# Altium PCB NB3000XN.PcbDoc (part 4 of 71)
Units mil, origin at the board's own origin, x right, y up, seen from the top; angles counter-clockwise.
Board outline 9527.56 x 6929.77 mil, 6 copper layers (Top Layer, GND+SHIELD, MidLayer1, MidLayer2, P2 - 3V3+5V0, Bottom Layer), stack 62.375 mil thick; 832 components, 1027 nets, 4655 pads, 4981 vias.
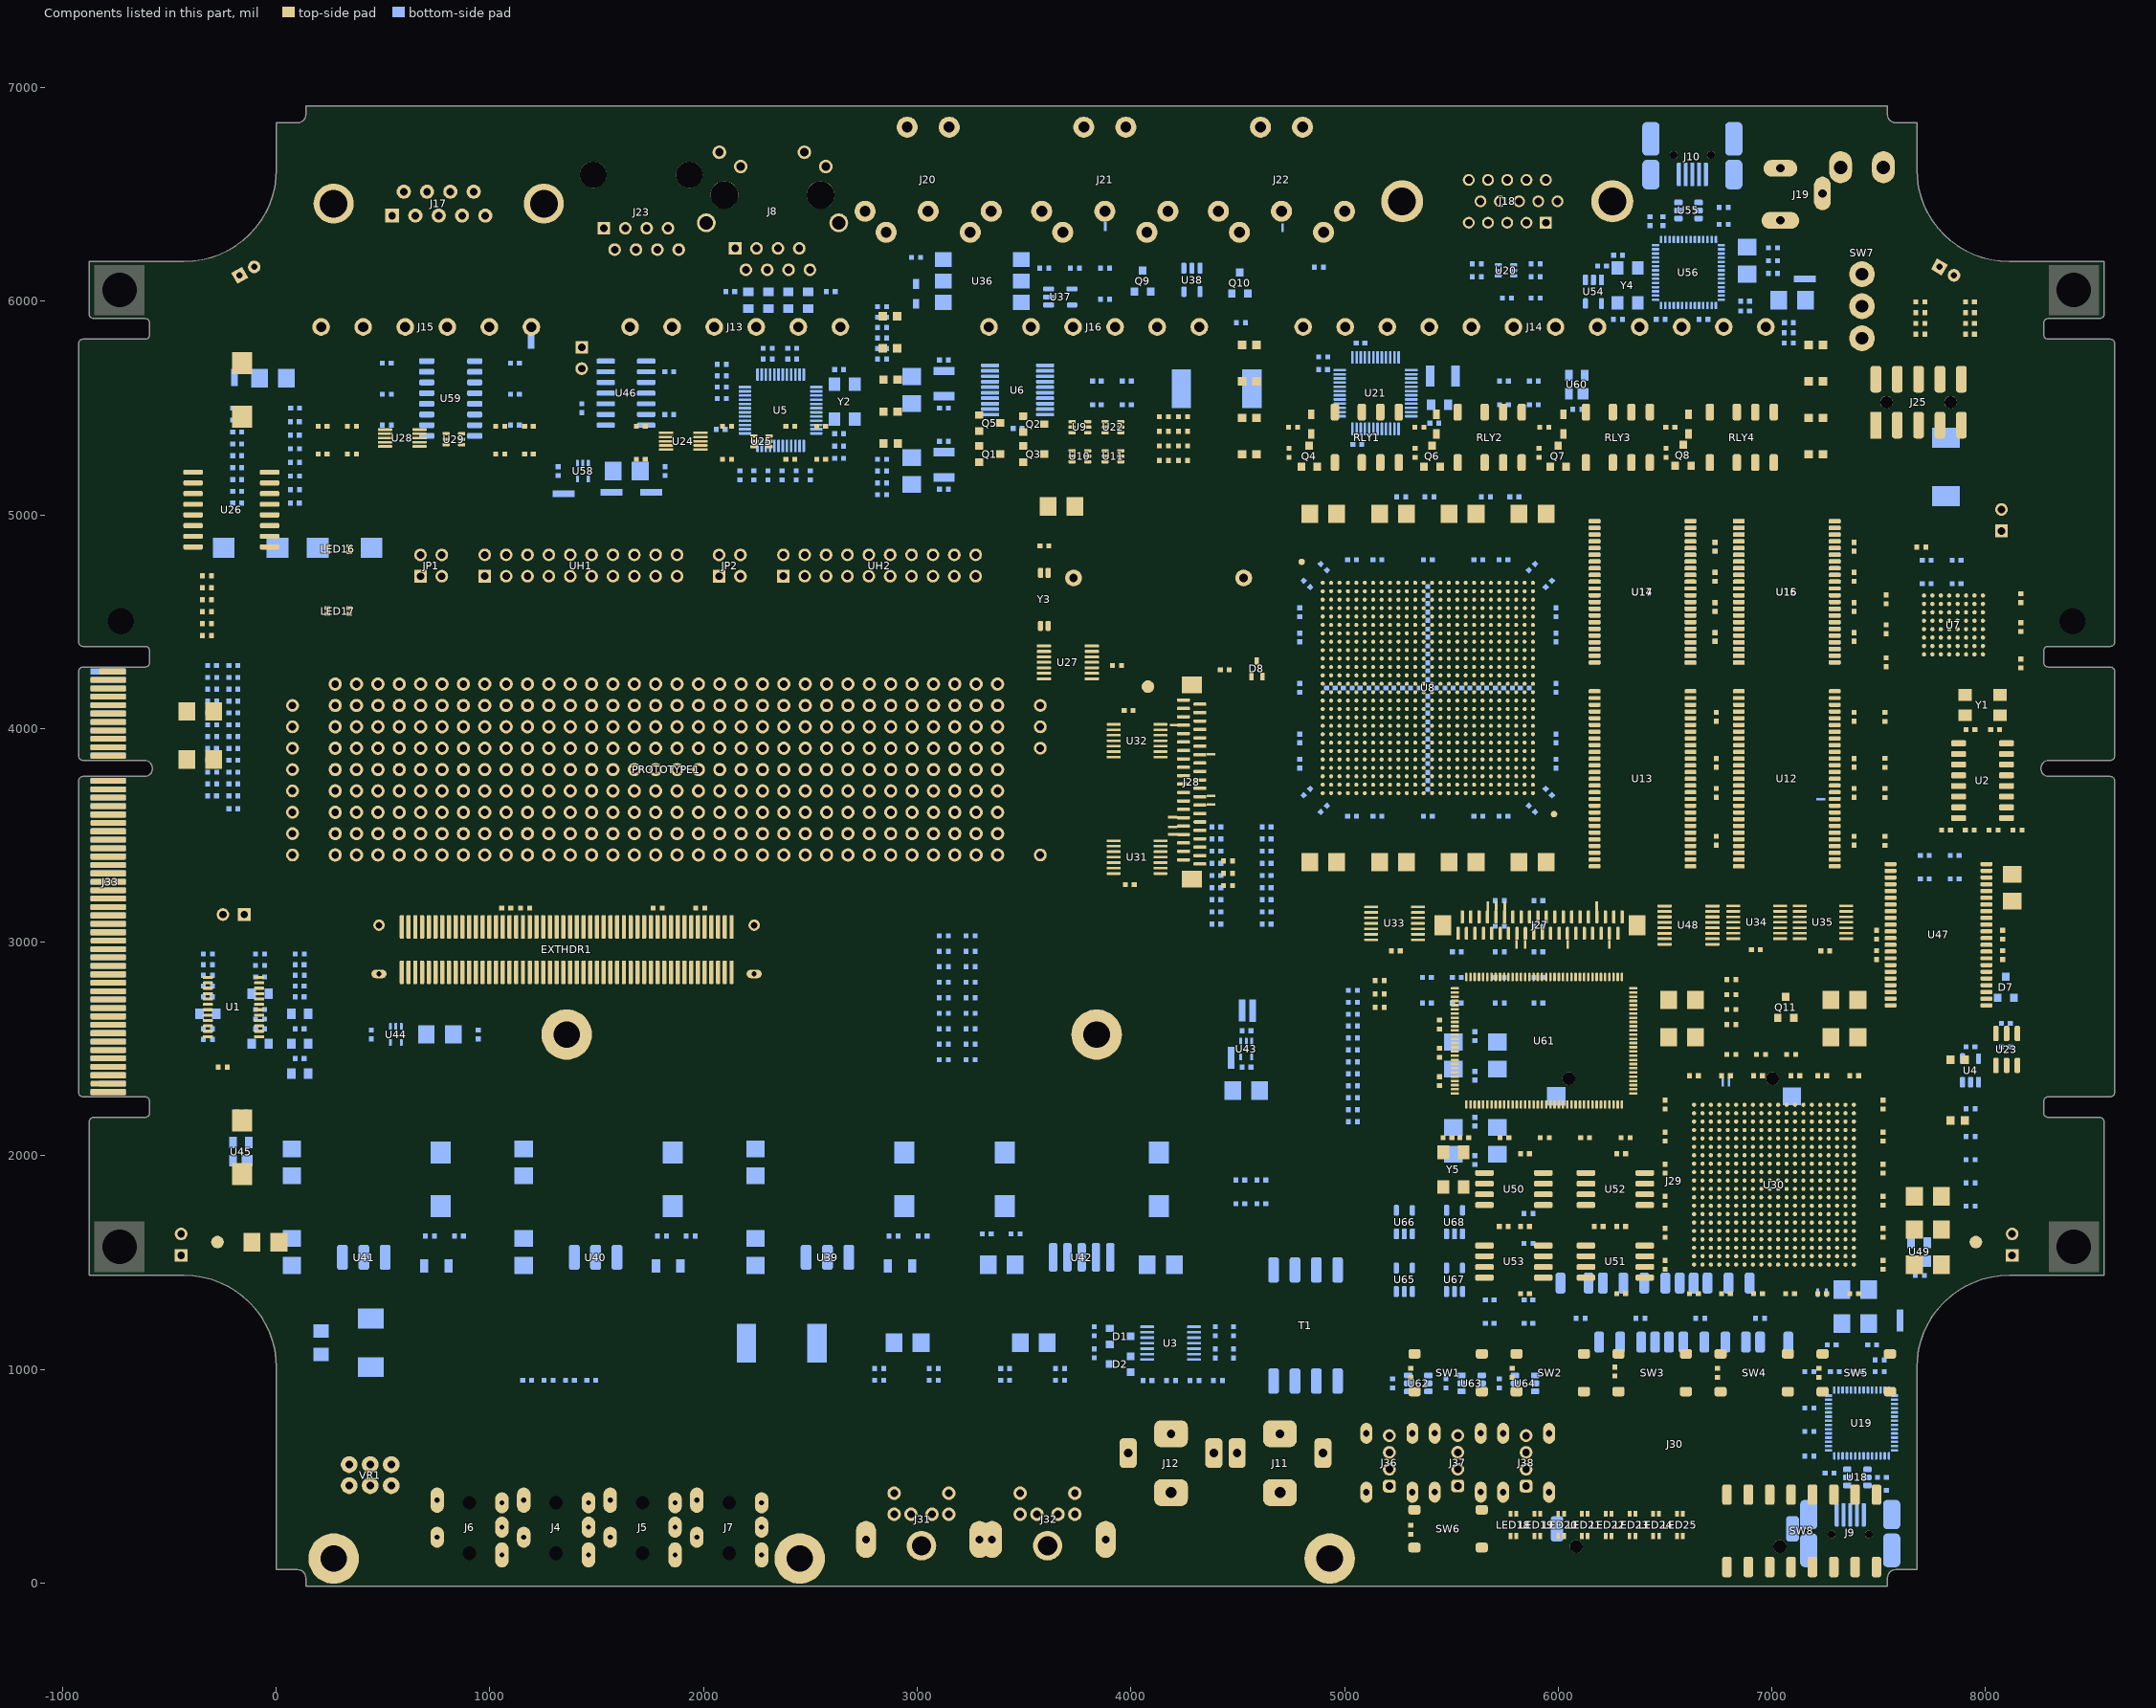
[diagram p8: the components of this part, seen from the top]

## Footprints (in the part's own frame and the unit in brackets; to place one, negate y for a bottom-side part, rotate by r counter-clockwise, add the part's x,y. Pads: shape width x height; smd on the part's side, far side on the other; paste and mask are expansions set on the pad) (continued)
S1204RGBSDJC [mm]
  rect 0.7x0.45 smd paste-1 mask+0: 1(1.313,-0.345)
  rect 0.7x0.45 smd paste-1 mask+0.102: 2(-1.313,-0.353) 3(-1.313,0.345)
  rect 0.7x0.45 smd paste-1: 4(1.313,0.343)
  silkscreen extent -2.19,-0.05 -2.09,0.05, body extent -1.49,-0.46 1.47,0.47, height 1.8
SC70_6L [mm]
  rrect50% 0.4x0.85 smd: 1(0,0) 2(0.65,0) 3(1.3,0) 4(1.3,1.85) 5(0.65,1.85) 6(0,1.85)
  silkscreen extent -0.8,-0.55 1.8,1.85, body extent -0.43,-0.38 1.73,2.22, height 0.64
SOD323 [mil] "SOD-323/SC-76; 2 Leads; Body 1.7 x 1.3 mm, (LxW)"
  rect 45x30 smd: 1(-46.26,0) 2(46.26,0)
  silkscreen extent -37,-30 37,30, body extent -39,-27 38,28, height 20
SOIC8-200-BODY [mm] "SOIC (JEDEC) 8 PIN, 200 mils body width"
  rrect50% 0.7x2.2 smd: 1(0,0) 2(1.27,0) 3(2.54,0) 4(3.81,0) 5(3.81,7) 6(2.54,7) 7(1.27,7) 8(0,7)
  silkscreen extent -1.34,0.54 4.4,5.4, body extent -0.7,0.12 4.71,6.88, height 1.06
SOIC127P600-14N [mm] "SOIC, 14-Leads, Body 8.7x3.9mm, Pitch 1.27mm, IPC Medium Density"
  rrect50% 2.2x0.6 smd: 1(-2.4,3.81) 2(-2.4,2.54) 3(-2.4,1.27) 4(-2.4,0) 5(-2.4,-1.27) 6(-2.4,-2.54) 7(-2.4,-3.81) 8(2.4,-3.81) 9(2.4,-2.54) 10(2.4,-1.27) 11(2.4,0) 12(2.4,1.27) 13(2.4,2.54) 14(2.4,3.81)
  silkscreen extent -2.53,-4.4 0.9,4.78, body extent -2.88,-4.28 2.92,4.28, height 1.75
SOIC127P600-16 [mm]
  rrect50% 0.7x1.8 smd: 1(-4.445,-2.85) 2(-3.175,-2.85) 3(-1.905,-2.85) 4(-0.635,-2.85) 5(0.635,-2.85) 6(1.905,-2.85) 7(3.175,-2.85) 8(4.445,-2.85) 9(4.445,2.85) 10(3.175,2.85) 11(1.905,2.85) 12(0.635,2.85) 13(-0.635,2.85) 14(-1.905,2.85) 15(-3.175,2.85) 16(-4.445,2.85)
  silkscreen extent -5.42,-2.72 5,1.1, body extent -4.9,-2.87 4.9,2.93, height 1.75
SOIC127P1030-16N [mm] "SOIC, 16-Leads, Body 10.3x7.5mm, Pitch 1.27mm, IPC Medium Density"
  rrect50% 2.3x0.6 smd: 1(-4.55,4.445) 2(-4.55,3.175) 3(-4.55,1.905) 4(-4.55,0.635) 5(-4.55,-0.635) 6(-4.55,-1.905) 7(-4.55,-3.175) 8(-4.55,-4.445) 9(4.55,-4.445) 10(4.55,-3.175) 11(4.55,-1.905) 12(4.55,-0.635) 13(4.55,0.635) 14(4.55,1.905) 15(4.55,3.175) 16(4.55,4.445)
  silkscreen extent -4.67,-5.25 3,5.42, body extent -4.9,-5.25 4.89,5.25, height 2.65
SOP65P780-20 [mm]
  rrect50% 0.45x2.15 smd: 1(-2.925,-3.275) 2(-2.275,-3.275) 3(-1.625,-3.275) 4(-0.975,-3.275) 5(-0.325,-3.275) 6(0.325,-3.275) 7(0.975,-3.275) 8(1.625,-3.275) 9(2.275,-3.275) 10(2.925,-3.275) 11(2.925,3.275) 12(2.275,3.275) 13(1.625,3.275) 14(0.975,3.275) 15(0.325,3.275) 16(-0.325,3.275) 17(-0.975,3.275) 18(-1.625,3.275) 19(-2.275,3.275) 20(-2.925,3.275)
  silkscreen extent -3.8,-3.4 3.75,1.8, body extent -3.33,-3.33 3.43,3.28, height 1
SOT65P210X80-5N [mm] "SOT23, 5-Leads, Body 2.0x2.1mm (max), Pitch 0.65mm, IPC Medium Density"
  rrect50% 0.8x0.35 smd: 1(-0.95,0.65) 2(-0.95,0) 3(-0.95,-0.65) 4(0.95,-0.65) 5(0.95,0.65)
  silkscreen extent -1.07,-1 0.15,1.5, body extent -1.02,-0.99 0.9,0.99, height 0.57
SOT95P230-3C [mm] "SOT23, 1=bottom-left, 2=bottom-right, 3=top"
  rect 0.9x0.95 smd: 1(-0.95,-1.25) 2(0.95,-1.25) 3(0,1.25)
  silkscreen extent -1.3,-0.38 1.3,1.25, body extent -1.14,-1.18 1.17,1.44, height 0.38
SOT95P230-3D [mm] "SOT23, 1=bottom-left, 2=top, 3=bottom-right"
  rect 0.9x0.95 smd: 1(-0.95,-1.25) 2(0,1.25) 3(0.95,-1.25)
  silkscreen extent -1.3,-0.38 1.3,1.25, body extent -1.14,-1.25 1.17,1.36, height 0.38
SOT95P280-5 [mm] "SOT-23/SC-74A; 5 Leads; Body 3.1 x 3 mm, inc. leads (LxW max)33"
  rrect50% 0.6x1.3 smd: 1(-0.95,-1.4) 2(0,-1.4) 3(0.95,-1.4) 4(0.95,1.4)
  rrect50% 0.6x1.25 smd: 5(-0.95,1.4)
  silkscreen extent -1.55,-0.9 1.55,0.9, body extent -1.45,-1.45 1.45,1.35, height 0.77
SOT143 [mm] "SOT-143; 4 Leads; Body 3 x 2.6 mm, inc. leads (LxW max)"
  rect 1.35x1.35 smd: 1(-0.75,-1.1)
  rect 0.9x1.35 smd: 2(0.95,-1.1) 3(0.95,1.1) 4(-0.95,1.1)
  silkscreen extent -1.88,-2.22 1.75,0.7, body extent -1.52,-1.5 1.51,1.46, height 0.8
SOT323-3AL [mm] "SOT323, 3-Leads, Body 2.0x1.3mm, Pitch 0.65mm, Lead Span 2.1mm, IPC High Density"
  rect 0.9x0.508 smd: 1(-0.9,0.65) 2(-0.9,-0.65) 3(0.9,0)
  silkscreen extent -1.02,-1.1 0.7,1.57, body extent -0.7,-1.1 0.7,1.1, height 1
SOT425-1 [mm] "LQFP128: plastic low profile quad flat package; 128 leads; body 14 x 20 x 1.4 mm"
  rrect50% 0.305x0.975 smd mask+0.05: 1(0,0) 2(0.5,0) 3(1,0) 4(1.5,0) 5(2,0) 6(2.5,0) 7(3,0) 8(3.5,0) 9(4,0) 10(4.5,0) 11(5,0) 12(5.5,0) 13(6,0) 14(6.5,0) 15(7,0) 16(7.5,0) 17(8,0) 18(8.5,0) 19(9,0) 20(9.5,0) 21(10,0) 22(10.5,0) 23(11,0) 24(11.5,0) 25(12,0) 26(12.5,0) 27(13,0) 28(13.5,0) 29(14,0) 30(14.5,0) 31(15,0) 32(15.5,0) 33(16,0) 34(16.5,0) 35(17,0) 36(17.5,0) 37(18,0) 38(18.5,0) 65(18.5,15.172) 66(18,15.172) 67(17.5,15.172) 68(17,15.172) 69(16.5,15.172) 70(16,15.172) 71(15.5,15.172) 72(15,15.172) 73(14.5,15.172) 74(14,15.172) 75(13.5,15.172) 76(13,15.172) 77(12.5,15.172) 78(12,15.172) 79(11.5,15.172) 80(11,15.172) 81(10.5,15.172) 82(10,15.172) 83(9.5,15.172) 84(9,15.172) 85(8.5,15.172) 86(8,15.172) 87(7.5,15.172) 88(7,15.172) 89(6.5,15.172) 90(6,15.172) 91(5.5,15.172) 92(5,15.172) 93(4.5,15.172) 94(4,15.172) 95(3.5,15.172) 96(3,15.172) 97(2.5,15.172) 98(2,15.172) 99(1.5,15.172) 100(1,15.172) 101(0.5,15.172) 102(0,15.172)
  rrect50% 0.975x0.305 smd mask+0.05: 39(19.861,1.32) 40(19.861,1.82) 41(19.861,2.32) 42(19.861,2.82) 43(19.861,3.32) 44(19.861,3.82) 45(19.861,4.32) 46(19.861,4.82) 47(19.861,5.32) 48(19.861,5.82) 49(19.861,6.32) 50(19.861,6.82) 51(19.861,7.32) 52(19.861,7.82) 53(19.861,8.32) 54(19.861,8.82) 55(19.861,9.32) 56(19.861,9.82) 57(19.861,10.32) 58(19.861,10.82) 59(19.861,11.32) 60(19.861,11.82) 61(19.861,12.32) 62(19.861,12.82) 63(19.861,13.32) 64(19.861,13.82) 103(-1.35,13.82) 104(-1.35,13.32) 105(-1.35,12.82) 106(-1.35,12.32) 107(-1.35,11.82) 108(-1.35,11.32) 109(-1.35,10.82) 110(-1.35,10.32) 111(-1.35,9.82) 112(-1.35,9.32) 113(-1.35,8.82) 114(-1.35,8.32) 115(-1.35,7.82) 116(-1.35,7.32) 117(-1.35,6.82) 118(-1.35,6.32) 119(-1.35,5.82) 120(-1.35,5.32) 121(-1.35,4.82) 122(-1.35,4.32) 123(-1.35,3.82) 124(-1.35,3.32) 125(-1.35,2.82) 126(-1.35,2.32) 127(-1.35,1.82) 128(-1.35,1.32)
  silkscreen extent -0.66,0.68 19.26,14.49, body extent -1.67,-0.34 20.2,15.54, height 1.61
STANDOFF_SOLDER_3MM#1 [mm] "Non-plated hole for 3mm Soldered Standoff"
  round 6 / inner round 5 / far side round 5 hole 3.15 mask+0.1: STAND(0,0)
  Top Layer circle w0.254: c0,0 r3.3
  Top Layer circle w1: c0,0 r2.2
  Bottom Layer lines w0.4: 3.3,3.3 3.3,-3.3 -3.3,-3.3 -3.3,3.3 3.3,3.3
  body extent -2.76,-2.76 2.74,2.74, height 8.5
STANDOFF_SOLDER_3MM#2 [mm] "Non-plated hole for 3mm Soldered Standoff"
  round 6 / inner round 5 / far side round 5 hole 3.15: STAND(0,0)
  Top Layer circle w0.254: c0,0 r3.3
  Top Layer circle w1: c0,0 r2.2
  Bottom Layer lines w0.635: 3.3,3.3 3.3,-3.3 -3.3,-3.3 -3.3,3.3 3.3,3.3
  body extent -2.76,-2.76 2.74,2.74, height 8.5
SW_DTSM-61NT/R [mil] "Switch, Push Button, Thru-Hole; 4 Leads; Body 8.5 x 8.5 mm (LxW typ); Row Spacing 9.0 mm; Pitch 4.5 mm"
  rrect50% 57x45 smd: 1(157.87,-88.58) 2(-157.48,-88.58) 3(157.87,88.19) 4(-157.48,88.19)
  silkscreen extent -124,-124 124,124, body extent -177,-122 177,122, height 177
T8019L-TNQ [mm]
  round 3.048 hole 1.5: 1(0,20.142) 2(0,23.952) 3(0,27.762)
  oval 2.7x3.81 hole 1.6: S1(2.54,7.442) S2(-2.54,7.442)
  silkscreen extent -3.43,0 3.43,26.11, body extent -3.5,-8.38 3.5,28.01, height 13
TESTPIN [mil]
  round 60 hole 35.43: 1(0,0)
  silkscreen extent -41,-39 156,39
TESTPOINT_ARRAY [mil]
  round 62 hole 35.43: 1(0,0) 2(100,0) 3(200,0) 4(300,0) 5(400,0) 6(500,0) 7(600,0) 8(700,0) 9(800,0) 10(900,0) 11(1000,0) 12(1100,0) 13(1200,0) 14(1300,0) 15(1400,0) 16(1500,0) 17(1600,0) 18(1700,0) 19(1800,0) 20(1900,0) 21(2000,0) 22(2100,0) 23(2200,0) 24(2300,0) 25(2400,0) 26(2500,0) 27(2600,0) 28(2700,0) 29(2800,0) 30(2900,0) 31(3000,0) 32(3100,0) A1(0,700) A2(100,700) A3(200,700) A4(300,700) A5(400,700) A6(500,700) A7(600,700) A8(700,700) A9(800,700) A10(900,700) A11(1000,700) A12(1100,700) A13(1200,700) A14(1300,700) A15(1400,700) A16(1500,700) A17(1600,700) A18(1700,700) A19(1800,700) A20(1900,700) A21(2000,700) A22(2100,700) A23(2200,700) A24(2300,700) A25(2400,700) A26(2500,700) A27(2600,700) A28(2700,700) A29(2800,700) A30(2900,700) A31(3000,700) A32(3100,700) B1(0,600) B2(100,600) B3(200,600) B4(300,600) B5(400,600) B6(500,600) B7(600,600) B8(700,600) B9(800,600) B10(900,600) B11(1000,600) B12(1100,600) B13(1200,600) B14(1300,600) B15(1400,600) B16(1500,600) B17(1600,600) B18(1700,600) B19(1800,600) B20(1900,600) B21(2000,600) B22(2100,600) B23(2200,600) B24(2300,600) B25(2400,600) B26(2500,600) B27(2600,600) B28(2700,600) B29(2800,600) B30(2900,600) B31(3000,600) B32(3100,600) C1(0,500) C2(100,500) C3(200,500) C4(300,500) C5(400,500) C6(500,500) C7(600,500) C8(700,500) C9(800,500) C10(900,500) C11(1000,500) C12(1100,500) C13(1200,500) C14(1300,500) C15(1400,500) C16(1500,500) C17(1600,500) C18(1700,500) C19(1800,500) C20(1900,500) C21(2000,500) C22(2100,500) C23(2200,500) C24(2300,500) C25(2400,500) C26(2500,500) C27(2600,500) C28(2700,500) C29(2800,500) C30(2900,500) C31(3000,500) C32(3100,500) D1(0,400) D2(100,400) D3(200,400) D4(300,400) D5(400,400) D6(500,400) D7(600,400) D8(700,400) D9(800,400) D10(900,400) D11(1000,400) D12(1100,400) D13(1200,400) D14(1300,400) D15(1400,400) D16(1500,400) D17(1600,400) D18(1700,400) D19(1800,400) D20(1900,400) D21(2000,400) D22(2100,400) D23(2200,400) D24(2300,400) D25(2400,400) D26(2500,400) D27(2600,400) D28(2700,400) D29(2800,400) D30(2900,400) D31(3000,400) D32(3100,400) E1(0,300) E2(100,300) E3(200,300) E4(300,300) E5(400,300) E6(500,300) E7(600,300) E8(700,300) E9(800,300) E10(900,300) E11(1000,300) E12(1100,300) E13(1200,300) E14(1300,300) E15(1400,300) E16(1500,300) E17(1600,300) E18(1700,300) E19(1800,300) E20(1900,300) E21(2000,300) E22(2100,300) E23(2200,300) E24(2300,300) E25(2400,300) E26(2500,300) E27(2600,300) E28(2700,300) E29(2800,300) E30(2900,300) E31(3000,300) E32(3100,300) F1(0,200) F2(100,200) F3(200,200) F4(300,200) F5(400,200) F6(500,200) F7(600,200) F8(700,200) F9(800,200) F10(900,200) F11(1000,200) F12(1100,200) F13(1200,200) F14(1300,200) F15(1400,200) F16(1500,200) F17(1600,200) F18(1700,200) F19(1800,200) F20(1900,200) F21(2000,200) F22(2100,200) F23(2200,200) F24(2300,200) F25(2400,200) F26(2500,200) F27(2600,200) F28(2700,200) F29(2800,200) F30(2900,200) F31(3000,200) F32(3100,200) G1(0,100) G2(100,100) G3(200,100) G4(300,100) G5(400,100) G6(500,100) G7(600,100) G8(700,100) G9(800,100) G10(900,100) G11(1000,100) G12(1100,100) G13(1200,100) G14(1300,100) G15(1400,100) G16(1500,100) G17(1600,100) G18(1700,100) G19(1800,100) G20(1900,100) G21(2000,100) G22(2100,100) G23(2200,100) G24(2300,100) G25(2400,100) G26(2500,100) G27(2600,100) G28(2700,100) G29(2800,100) G30(2900,100) G31(3000,100) G32(3100,100) H1(0,800) H2(100,800) H3(200,800) H4(300,800) H5(400,800) H6(500,800) H7(600,800) H8(700,800) H9(800,800) H10(900,800) H11(1000,800) H12(1100,800) H13(1200,800) H14(1300,800) H15(1400,800) H16(1500,800) H17(1600,800) H18(1700,800) H19(1800,800) H20(1900,800) H21(2000,800) H22(2100,800) H23(2200,800) H24(2300,800) H25(2400,800) H26(2500,800) H27(2600,800) H28(2700,800) H29(2800,800) H30(2900,800) H31(3000,800) H32(3100,800)
  silkscreen extent -136,-149 3234,958
TO254P-3N [mm] "D2-PAK, 3-Pads, IPC Medium Density"
  rrect50% 3x1.3 smd: 1(-6.35,2.54) 2(-6.35,0) 3(-6.35,-2.54)
  Top Layer region: 9.253,5.949 9.253,-6.051 -4.639,-6.051 -4.639,5.949
  silkscreen extent -8.73,-6.05 9.27,5.95, body extent -7.34,-5.09 8.1,5.08, height 2.53
TO-263-2 [mm]
  rrect50% 1x3.4 smd: 1(-3.4,0) 2(-1.7,0) 3(0,0) 4(1.7,0) 5(3.4,0)
  Top Layer region: -5.949,15.619 6.051,15.619 6.051,2.032 -5.949,2.032
  silkscreen extent -5.95,-2.38 6.05,15.62, body extent -5.11,-0.87 5.05,13.77, height 4.57
TRC-005 [mm] "RCA Phono Jack, Right Angle, Thru-Hole, Body 20.8 x 9.8 x 11 mm (LxWxH)"
  rrect50% 3.2x4 hole 1.3 slot 2.5 at 90 deg: 1(-7,0)
  rrect50% 3.556x2.032 hole 1 slot 2.5 at 0 deg: 2(-2.3,5.1) 3(-2.3,-5.1)
  rrect50% 3.2x4 hole 1 slot 2.5 at 90 deg: 4(0,0)
  silkscreen extent -20.05,-4.9 0.75,4.9, body extent -20.02,-5.26 0.48,5.52, height 13.58
TSH-3675 [mm]
  oval 3x1.6 hole 0.6 slot 2 at 0 deg: 1(-0.2,3.85) 2(6.3,-3.85)
  oval 2.5x1.6 hole 0.6 slot 1.5 at 0 deg: 3(6,3.85) 10(1.9,-3.85) 11(3.1,3.85)
  round 1.3 hole 1.6 unplated: 12(6,0) 13(0,0)
  silkscreen extent -6,-4.75 9,4.75, body extent -5.97,-4.72 9.02,4.78, height 5
TSM-105-01-DV [mil] "SMT 100mil space smt pin header"
  rect 50x125 smd: 1(0,-215)
  rrect50% 50x125 smd: 2(0,0) 3(100,-215) 4(100,0) 5(200,-215) 6(200,0) 7(300,-215) 8(300,0) 9(400,-215) 10(400,0)
  round 59.05 hole 59.06 unplated mask+1.5: PEGA(50,-108) PEGB(350,-108)
  silkscreen extent -35,-287 435,73, body extent -52,-253 448,37, height 10
TSOP65P640-14AN [mm] "TSOP, 14-Leads, Body 5x4.4mm, Pitch 0.65mm, IPC Medium Density"
  rrect50% 1.7x0.35 smd: 1(-2.85,1.95) 2(-2.85,1.3) 3(-2.85,0.65) 4(-2.85,0) 5(-2.85,-0.65) 6(-2.85,-1.3) 7(-2.85,-1.95) 8(2.85,-1.95) 9(2.85,-1.3) 10(2.85,-0.65) 11(2.85,0) 12(2.85,0.65) 13(2.85,1.3) 14(2.85,1.95)
  silkscreen extent -2.97,-2.55 1.6,2.8, body extent -3.05,-2.53 3.34,2.47, height 0.64
TSOP65P640-16AN [mm] "TSOP, 16-Leads, Body 5x4.4mm, Pitch 0.65mm, IPC Medium Density"
  rrect50% 1.7x0.35 smd: 1(-2.85,2.275) 2(-2.85,1.625) 3(-2.85,0.975) 4(-2.85,0.325) 5(-2.85,-0.325) 6(-2.85,-0.975) 7(-2.85,-1.625) 8(-2.85,-2.275) 9(2.85,-2.275) 10(2.85,-1.625) 11(2.85,-0.975) 12(2.85,-0.325) 13(2.85,0.325) 14(2.85,0.975) 15(2.85,1.625) 16(2.85,2.275)
  silkscreen extent -2.97,-2.55 1.6,3.12, body extent -3.3,-2.38 3.37,2.77, height 0.64
TSOP80P1176-44 [mm]
  rrect50% 0.508x1.4 smd: 1(-8.4,-5.7) 2(-7.6,-5.7) 3(-6.8,-5.7) 4(-6,-5.7) 5(-5.2,-5.7) 6(-4.4,-5.7) 7(-3.6,-5.7) 8(-2.8,-5.7) 9(-2,-5.7) 10(-1.2,-5.7) 11(-0.4,-5.7) 12(0.4,-5.7) 13(1.2,-5.7) 14(2,-5.7) 15(2.8,-5.7) 16(3.6,-5.7) 17(4.4,-5.7) 18(5.2,-5.7) 19(6,-5.7) 20(6.8,-5.7) 21(7.6,-5.7) 22(8.4,-5.7) 23(8.4,5.7) 24(7.6,5.7) 25(6.8,5.7) 26(6,5.7) 27(5.2,5.7) 28(4.4,5.7) 29(3.6,5.7) 30(2.8,5.7) 31(2,5.7) 32(1.2,5.7) 33(0.4,5.7) 34(-0.4,5.7) 35(-1.2,5.7) 36(-2,5.7) 37(-2.8,5.7) 38(-3.6,5.7) 39(-4.4,5.7) 40(-5.2,5.7) 41(-6,5.7) 42(-6.8,5.7) 43(-7.6,5.7) 44(-8.4,5.7)
  silkscreen extent -9.29,-5.7 9.26,4.45, body extent -9.24,-5.95 9.26,5.84, height 1
TSOP80P1176-54 [mm] "Plastic Small Outline; 54 Leads; Body Width 10.16 mm"
  rrect50% 0.508x1.4 smd: 1(-10.4,-5.7) 2(-9.6,-5.7) 3(-8.8,-5.7) 4(-8,-5.7) 5(-7.2,-5.7) 6(-6.4,-5.7) 7(-5.6,-5.7) 8(-4.8,-5.7) 9(-4,-5.7) 10(-3.2,-5.7) 11(-2.4,-5.7) 12(-1.6,-5.7) 13(-0.8,-5.7) 14(0,-5.7) 15(0.8,-5.7) 16(1.6,-5.7) 17(2.4,-5.7) 18(3.2,-5.7) 19(4,-5.7) 20(4.8,-5.7) 21(5.6,-5.7) 22(6.4,-5.7) 23(7.2,-5.7) 24(8,-5.7) 25(8.8,-5.7) 26(9.6,-5.7) 27(10.4,-5.7) 28(10.4,5.7) 29(9.6,5.7) 30(8.8,5.7) 31(8,5.7) 32(7.2,5.7) 33(6.4,5.7) 34(5.6,5.7) 35(4.8,5.7) 36(4,5.7) 37(3.2,5.7) 38(2.4,5.7) 39(1.6,5.7) 40(0.8,5.7) 41(0,5.7) 42(-0.8,5.7) 43(-1.6,5.7) 44(-2.4,5.7) 45(-3.2,5.7) 46(-4,5.7) 47(-4.8,5.7) 48(-5.6,5.7) 49(-6.4,5.7) 50(-7.2,5.7) 51(-8,5.7) 52(-8.8,5.7) 53(-9.6,5.7) 54(-10.4,5.7)
  silkscreen extent -11.33,-5.67 11.15,4.4, body extent -11.23,-5.96 11.19,5.97, height 1
TSOP95P275-6 [mm]
  rrect50% 0.7x1 smd: 1(-0.95,-1.2) 2(0,-1.2) 3(0.95,-1.2) 4(0.95,1.2) 5(0,1.2) 6(-0.95,1.2)
  silkscreen extent -1.87,-1.32 1.5,0.7, body extent -1.49,-1.3 1.51,1.3, height 0.8
TSQFP50P900X900-48 [mm]
  rrect50% 1.5x0.305 smd: 1(-4.25,2.75) 2(-4.25,2.25) 3(-4.25,1.75) 4(-4.25,1.25) 5(-4.25,0.75) 6(-4.25,0.25) 7(-4.25,-0.25) 8(-4.25,-0.75) 9(-4.25,-1.25) 10(-4.25,-1.75) 11(-4.25,-2.25) 12(-4.25,-2.75) 25(4.25,-2.75) 26(4.25,-2.25) 27(4.25,-1.75) 28(4.25,-1.25) 29(4.25,-0.75) 30(4.25,-0.25) 31(4.25,0.25) 32(4.25,0.75) 33(4.25,1.25) 34(4.25,1.75) 35(4.25,2.25) 36(4.25,2.75)
  rrect50% 0.305x1.5 smd: 13(-2.75,-4.25) 14(-2.25,-4.25) 15(-1.75,-4.25) 16(-1.25,-4.25) 17(-0.75,-4.25) 18(-0.25,-4.25) 19(0.25,-4.25) 20(0.75,-4.25) 21(1.25,-4.25) 22(1.75,-4.25) 23(2.25,-4.25) 24(2.75,-4.25) 37(2.75,4.25) 38(2.25,4.25) 39(1.75,4.25) 40(1.25,4.25) 41(0.75,4.25) 42(0.25,4.25) 43(-0.25,4.25) 44(-0.75,4.25) 45(-1.25,4.25) 46(-1.75,4.25) 47(-2.25,4.25) 48(-2.75,4.25)
  silkscreen extent -4.75,-4 4,4, body extent -4.04,-4.14 4.01,4.24, height 0.85
TSQFP50P900X900_HS-48 [mm]
  rrect50% 1.5x0.305 smd: 1(-4.25,2.75) 2(-4.25,2.25) 3(-4.25,1.75) 4(-4.25,1.25) 5(-4.25,0.75) 6(-4.25,0.25) 7(-4.25,-0.25) 8(-4.25,-0.75) 9(-4.25,-1.25) 10(-4.25,-1.75) 11(-4.25,-2.25) 12(-4.25,-2.75) 25(4.25,-2.75) 26(4.25,-2.25) 27(4.25,-1.75) 28(4.25,-1.25) 29(4.25,-0.75) 30(4.25,-0.25) 31(4.25,0.25) 32(4.25,0.75) 33(4.25,1.25) 34(4.25,1.75) 35(4.25,2.25) 36(4.25,2.75)
  rrect50% 0.305x1.5 smd: 13(-2.75,-4.25) 14(-2.25,-4.25) 15(-1.75,-4.25) 16(-1.25,-4.25) 17(-0.75,-4.25) 18(-0.25,-4.25) 19(0.25,-4.25) 20(0.75,-4.25) 21(1.25,-4.25) 22(1.75,-4.25) 23(2.25,-4.25) 24(2.75,-4.25) 37(2.75,4.25) 38(2.25,4.25) 39(1.75,4.25) 40(1.25,4.25) 41(0.75,4.25) 42(0.25,4.25) 43(-0.25,4.25) 44(-0.75,4.25) 45(-1.25,4.25) 46(-1.75,4.25) 47(-2.25,4.25) 48(-2.75,4.25)
  Top Layer region: -2.25,2.25 2.25,2.25 2.25,-2.25 -2.25,-2.25
  silkscreen extent -4.75,-4 4,4, body extent -4.07,-4.14 3.98,4.24, height 0.8
TSSOP14 [mm]
  rrect50% 1.65x0.305 smd: 1(0,0) 2(0,-0.65) 3(0,-1.3) 4(0,-1.95) 5(0,-2.6) 6(0,-3.25) 7(0,-3.9) 8(5.55,-3.9) 9(5.55,-3.25) 10(5.55,-2.6) 11(5.55,-1.95) 12(5.55,-1.3) 13(5.55,-0.65) 14(5.55,0)
  silkscreen extent 0.52,-4.19 4.37,0.7, body extent -0.4,-4.49 6,0.61, height 1.19
TSSOP50P490-10AN [mm] "TSSOP, 10-Leads, Body 3x3mm, Pitch 0.5mm, IPC Medium Density"
  rrect50% 1.7x0.305 smd: 1(-2.05,1) 2(-2.05,0.5) 3(-2.05,0) 4(-2.05,-0.5) 5(-2.05,-1) 6(2.05,-1) 7(2.05,-0.5) 8(2.05,0) 9(2.05,0.5) 10(2.05,1)
  silkscreen extent -2.17,-1.6 0.8,1.82, body extent -2.4,-1.6 2.4,1.6, height 1.1
TSSOP-24 [mm]
  rrect50% 0.36x1.18 smd mask+0.051: 1(0,0) 2(0.64,0) 3(1.28,0) 4(1.92,0) 5(2.56,0) 6(3.2,0) 7(3.84,0) 8(4.48,0) 9(5.12,0) 10(5.76,0) 11(6.4,0) 12(7.04,0) 13(7.04,6.1) 14(6.4,6.1) 15(5.76,6.1) 16(5.12,6.1) 17(4.48,6.1) 18(3.84,6.1) 19(3.2,6.1) 20(2.56,6.1) 21(1.92,6.1) 22(1.28,6.1) 23(0.64,6.1) 24(0,6.1)
  silkscreen extent -0.17,1.37 7.12,4.9, body extent -0.3,0.02 7.25,6.36, height 0.9
XTAL-200X126-4 [mil] "CRYSTAL SMD 200x126x44 mils, 4 pads"
  rect 63x55 smd: 1(-81.5,-47.5) 2(81.5,-47.5) 3(81.5,47.5) 4(-81.5,47.5)
  silkscreen extent -30,-72 30,72, body extent -114,-52 113,51, height 39

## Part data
"Altium Logo BOT1": library part D-000-0003, "Altium Logo for PCB"
BT1: library part D-302-0000, "Lithium Battery Holder for CR2032 3V Cell"
C1 C2 C106 C107 C129 C133 C137 C138 C141: library part D-101-0088, "Capacitor, Tantalum, 220uF 10% 10V MCCT-D (7343-31)"
C3 C4 C36 C40 C49 C61 C62 C89 C93 C111 C115 C126 C128 C130 C132 C134 C136 C139 C140 C143 C146 C171 C175 C182 C184 C185 C189 C190 C191 C200 C201 C202 C203 C260 C265 C266 C267 C276 C277 C278 C279 C340 C341 C342: library part D-101-0007, "Capacitor, Tantalum, 10uF 10% 20V MCCT-B (3528)"
C5 C6 C8 C9 C10 C11 C12 C14 C15 C16 C17 C108 C109 C110 C121 C122 C123 C124 C125 C142 C144 C145 C147 C152 C181 C183: library part D-101-0131, "Capacitor, Ceramic, 1uF 10% 10V 0402 (1005) X5R"
C7 C13 C18: library part D-101-0132, "Capacitor, Ceramic, 4.7nF 10% 10V 0402 (1005) X7R"
C19 C20 C23 C25 C27 C31 C99: library part D-101-0087, "Capacitor, Ceramic, 10uF 10% 10V 0805 (2012) X5R"
C21 C22 C24 C26: library part D-101-0062, "Capacitor, Ceramic, 100nF 10% 16V 0402 (1005) X7R"
C28 C32: library part D-101-0064, "Capacitor, Ceramic, 220pF 5% 50V 0402 (1005) COG"
C29 C30 C57 C58 C59 C67 C68 C69 C70 C73 C74 C77 C78 C83 C84 C85 C86 C155 C156 C158 C160 C162 C164 C196 C197 C198 C199 C231 C232 C233 C234 C235 C236 C237 C238 C239 C240 C241 C242 C243 C244 C245 C246 C248 C250 C251 C253 C254 C256 C258 C272 C273 C274 C275 C307 C308 C309 C310 C311 C312 C313 C314 C315 C316 C317 C318 C319 C320 C321 C322 C324 C326 C327 C329 C330 C332 C334: library part D-101-0077, "Capacitor, Ceramic, 10nF 10% 16V 0402 (1005) X7R"
C33 C34: library part D-101-0075, "Capacitor, Ceramic, 15pF 5% 50V 0402 (1005)"
C35 C37 C38 C39 C55 C56 C60 C63 C64 C65 C66 C71 C72 C75 C76 C79 C80 C81 C82 C88 C90 C91 C92 C94 C95 C96 C97 C98 C100 C105 C112 C113 C114 C116 C148 C149 C150 C151 C153 C154 C159 C161 C163 C165 C168 C170 C172 C173 C174 C176 C177 C187 C192 C193 C194 C195 C215 C216 C217 C218 C219 C220 C221 C222 C223 C224 C225 C226 C227 C228 C229 C247 C249 C252 C255 C257 C259 C268 C269 C270 C271 C291 C292 C293 C294 C295 C296 C297 C298 C299 C300 C301 C302 C303 C304 C305 C323 C325 C328 C331 C333 C335 C336 C337 C338 C339: library part D-101-0080, "Capacitor, Ceramic, 0.1uF 10% 16V 0402 (1005) X7R"
C41 C42 C43 C44 C47 C48 C50 C51 C52 C53 C54: library part D-101-0045, "Capacitor, Ceramic, 0.1uF 25V 0402 (1005)"
C45 C46 C157 C166 C167 C169: library part D-101-0059, "Capacitor, Ceramic, 22pF 5% 50V 0402 (1005) COG"
C87: library part D-101-0019, "Capacitor, Ceramic, 4.7nF 20% 250V Panasonic BC J Lead (CAPM7163) Y5V"
C101 C102 C103 C104 C117 C118 C119 C120: library part D-101-0133, "Capacitor, Ceramic, 33nF 10% 25V 0402 (1005) X7R"
C127 C131 C135: library part D-101-0027, "Capacitor, Ceramic, 1uF 10% 25V 1206 (3216) X7R"
C186: library part D-101-0116, "Capacitor, Ceramic, 220nF 10% 16V 0402 (1005) X5R"
D1 D2: library part D-151-0002, "Schottky Diode, BAT54 30V 200mA 30V SOT-23"
D3 D4 D5 D6 D9: library part D-151-0004, "Schottky Diode, 400mA"
D7: library part D-150-0005, "Zener Diode, 3.3V"
D8: library part D-155-0001, "BAT54CW, SOT-323 Plastic-Encapsulated Diode"
D10: library part D-150-0001, "Zener Diode, 5V 5W"
EXTHDR1: library part D-300-0026, "Connector, Molex Docking Station 100 Pin Female 53751"
F1 F2: library part D-106-0000, "Mutifuse, SMD 5A"
FD1 FD2 FD3: library part D-004-0001, "Fiducial - Round 1.5mm Top-Bottom"
J1 J2 J3 J24 J26: library part D-300-0020, "Header IDC, 2 x 1 Pin Vertical 2.54mm Pitch (Non-Boxed, Male)"
J4 J7: library part D-300-0033, "Connector, 3.5mm Stereo Audio Socket, Black, 2 break contacts (normals) and 2 auxiliary make contacts"
J5: library part D-300-0031, "Connector, 3.5mm Stereo Audio Socket, Green, 2 break contacts (normals) and 2 auxiliary make contacts"
J6: library part D-300-0032, "Connector, 3.5mm Stereo Audio Socket, Blue, 2 break contacts (normals) and 2 auxiliary make contacts"
J8: library part D-300-0119, "Socket, 1x1 Tab-DOWN R/A 8-Way RJ45"
J9 J10: library part D-300-0009, "USB, MINI, SMD,  Molex"
J11 J12: library part CON-RCA-RA, "Connector, TRC-005-4 , Black RCA Phono Jack, Right Angle, Thru-Hole, Snap-In"
J13 J15 J16: library part D-300-0122, "Socket, Screw Terminal Block, 6 Way, 5.0mm pitch, 45 degree angle, Through-hole"
J14: library part D-300-0123, "Socket, Screw Terminal Block, 12 Way, 5.0mm pitch, 45 degree angle, Through-hole"
J17: library part D-300-0120, "Connector, DB9 R/A Through-hole Male"
J18: library part D-300-0121, "Socket, High-Density DB15 (HD15) R/A Female Through-hole"
J19: library part D-300-0007, "Connector, 3 Conductor Power Jack 2 break 2 aux contacts"
J20 J21 J22: library part D-300-0118, "Socket, 5-way R/A DIN"
J23: library part D-300-0117, "Socket, PC Jack 8-Way, R/A Low-profile"
J25: library part D-300-0076, "Non-Boxed Header IDC, 2 X 5 Pin SMD"
J27 J28: library part D-300-0125, "Header FFC, 2x20 pin Vertical, 0.5mm"
J29 J30: library part D-300-0126, "Secure Digital Card Socket"
J31 J32: library part D-300-0124, "MINI DIN R/A F/SHLD 6P GOLD PLATED; Black"
J33: library part D-300-0115, "Connector, PCI Express, Used for Automatic Test Equipment (ATE)"
J34 J35: library part D-300-0131, "PH Series 2 x 1 Pin Vertical 2.0mm Pitch (Male)"
J36 J37 J38: library part D-300-0127, "CONNECTOR USB RT ANG RECEPT TYPE A"
JP1 JP2: library part D-300-0019, "Header IDC, 2 x 2 Pin Vertical 2.54mm Pitch (Non-Boxed, Male)"
L1 L2: library part D-102-0006, "Inductor, Coil 22uH  1210 (3225) LQH32CN220K21L"
L3: library part D-102-0005, "Inductor, 4.7uH 650mA 0.15R 1210 (3225) LQH32CN4R7M11L"
LED1 LED3 LED4: library part D-153-0002
LED2 LED5 LED8 LED9 LED10 LED12: library part D-153-0007
LED6 LED11 LED13 LED14 LED15: library part D-153-0006
LED7: library part D-153-0009, "LED, Red 0603 (1608) 63mCd"
LED16 LED17 LED18 LED19 LED20 LED21 LED22 LED23 LED24 LED25: library part D-153-0020, "SASEN LED, RGB, SMD"
LOGO1: library part D-000-0000
NT1 NT11: library part D-002-0004, "Net-Tie, Surface Mount, 2 x 2.0mm x 0.8mm SMT Pads - For 0.8mm Track"
NT4 NT5 NT6 NT7 NT46 NT47 NT48: library part D-002-0002, "Net-Tie, Surface Mount, 2 x 0.4mm x 0.2mm SMT Pads - For 0.2mm Track"
NT10 NT17 NT18 NT19 NT26 NT27 NT28 NT29 NT30 NT31 NT33 NT34 NT35 NT36 NT37 NT38 NT39 NT40 NT41 NT42 NT43 NT44 NT45: library part D-002-0003, "Net-Tie, Surface Mount, 2 x 1.6mm x 0.8mm SMT Pads - For 0.8mm Track"
PB_MH1 PB_MH2 PB_MH3 PB_MH4 PB_MH5: library part D-306-0001, "Spacer, 8.5mm GOLD, Splitted bottom, Female M3-thread"
PCB1: library part D-810-0050, "NB2STR01 Blank PCB - NanoBoard  Starter kit"
PROTOTYPE1: library part D-006-0002, "Test Point Array"
Q1 Q2 Q3 Q5 Q11: library part D-158-0005, "N-channel Enhancement Mode Field-effect Transistor;  5.8A/30V"
Q4 Q6 Q7 Q8 Q9 Q10: library part D-158-0002, "N-channel Enhancement Mode Field-effect Transistor"
R1 R14: library part D-100-0098, "Resistor, 3K3 1% 0402 (1005)"
R2 R5 R6 R7 R10 R11 R12 R13 R15 R21 R35 R38 R110 R137 R138 R208 R247 R260 R272 R273 R274 R275 R276: library part D-100-0130, "Resistor, 10K 1% 0402 (1005)"
R3 R4 R215: library part D-100-0092, "Resistor, 47K 1% 0402 (1005)"
R8: library part D-100-0114, "Resistor, 22K 1% 0402 (1005)"
R9 R141 R142: library part D-100-0132, "Resistor, 100K 1% 0402 (1005)"
R16 R17 R18 R19 R20 R33: library part D-100-0102, "Resistor, 33R 1% 0402 (1005)"
R22 R25 R26 R27 R41 R42 R43 R44 R45 R46 R47 R50 R51 R52 R57 R59 R60 R61 R64 R65 R70 R73 R76 R77 R82 R83 R86 R87 R98 R102 R103 R104 R105 R106 R107 R113 R114 R115 R131 R148 R154 R161 R162 R163 R216 R217 R218 R219 R224 R225 R226 R227 R232 R236 R237 R238 R239 R240 R241 R242 R243 R248 R250 R251 R252 R253 R254 R255 R256 R271 R277 R278 R279 R280 R281 R282 R283: library part D-100-0088, "Resistor, 4K7 1% 0402 (1005)"
R23 R24 R116: library part D-100-0096, "Resistor, 430R 1% 0402 (1005)"
R28 R29 R100 R101 R153: library part D-100-0085, "Resistor, 5R6 1% 0402 (1005)"
R30 R53 R56 R91 R93 R95 R97 R124 R126 R128 R130 R139 R140 R143 R144: library part D-100-0121, "Resistor, 1K 1% 0402 (1005)"
R31 R32 R96 R125 R127 R129 R198 R200 R201 R203 R204 R205 R212 R214: library part D-100-0126, "Resistor, 120R 1% 0402 (1005)"
R34 R36: library part D-100-0001, "Resistor, 75R 1% 0402"
R37 R68 R69 R71 R72 R74 R75 R78 R79 R80 R81 R84 R85 R88 R89 R147 R209 R210 R211 R220 R221 R222 R223 R228 R229 R230 R231 R233 R267 R268 R269 R270: library part D-100-0131, "Resistor, 100R 1% 0402 (1005)"
R39 R40: library part D-100-0111, "Resistor, 270R 1% 0402 (1005)"
R48 R49 R54 R55: library part D-100-0017, "Resistor, 49R9 1% 0805 (2012)"
R58 R62 R63 R66 R67 R132 R195: library part D-100-0093, "Resistor, 470R 1% 0402 (1005)"
R90 R92 R94 R112 R123 R133 R134 R135 R136 R149 R150 R151 R152 R196 R244 R249: library part D-100-0108, "Resistor, 27R 1% 0402 (1005)"
R99 R145 R146 R155 R156 R157 R158 R159 R160 R234 R235 R264 R265 R266: library part D-100-0107, "Resistor, 2K2 1% 0402 (1005)"
R108 R245: library part D-100-0105, "Resistor, 2K7 1% 0402 (1005)"
R109 R246: library part D-100-0086, "Resistor, 5K6 1% 0402 (1005)"
R111: library part D-100-0059, "Resistor, 10M 1%1206 (3216)"
R117 R118 R119 R120 R121 R122 R164 R165 R166 R167 R168 R169 R170 R171 R172 R173 R174 R175 R176 R177 R178 R179 R180 R181 R182 R183 R184 R185 R186 R187 R188 R189 R190 R191 R192 R193 R261 R262 R263: library part D-100-0005, "Resistor, 150R 1% 0402 (1005)"
R194 R197 R199: library part D-100-0115, "Resistor, 220R 1% 0402 (1005)"
R202: library part D-100-0174, "Resistor, 56R 1% 0402"
R206: library part D-100-0116, "Resistor, 200R 1% 0402 (1005)"
R207: library part D-100-0137, "Resistor, 0R 5% 0402 (1005)"
R257 R258 R259: library part D-100-0002, "Resistor, 12K 1% 0402"
RLY1 RLY2 RLY3 RLY4: library part D-313-0001, "Relay, Tyco IM03GR"
SW1 SW2 SW3 SW4 SW5 SW6: library part D-301-0001, "Switch, SPNO Push Button SMD"
SW7: library part D-301-0000, "Switch, SPDT Subminiature Toggle"
SW8: library part D-301-0018, "Switch, SPST, Surface Mount DIP, 8-way"
T1: library part D-107-0004, "Transformer, 1:1, SMD, 0 to 70 deg C,  1 to 7 Mbps, 500Vrms min"
TP1 TP2 TP3 TP4 TP5 TP6 TP7 TP8 TP9 TP10 TP11 TP12: library part D-006-0000, "Test Point, PCB Mount with Silkscreen Box"
U1: library part D-201-0003, "CS4270; 24-Bit, 192 kHz Stereo Audio CODEC"
U2: library part D-206-0000, "ICS307-02, SPI Programmable Clock Generator"
U3: library part D-205-0010, "74HCU04, HEX Inverter, Unbuffered"
U4 U37 U38 U54 U65 U66 U67 U68: library part D-205-0001, "SN74LVC1G04DBV, Single Inverter Gate, 1.65-V to 5.5-V"
U5: library part D-221-0000, "RTL8201CL-VD, Single-Chip/Single-Port 10/100 Fast Ethernet Phyceiver"
U6: library part D-205-0000, "SN74LVC244ADBR,  Octal Buffer/Driver with 3-State Outputs, 2.0V - 3.6V"
U7: library part D-262-0008, "IC Flash, S29GL128P11FFI010 128 Megabit 3.0V Page Mode Flash Memory"
U8: library part D-241-0015, "FPGA, Xilinx Spartan 3AN-1400 FG676"
U9 U10 U11 U20 U22 U25 U29: library part D-157-0000, "TVS Diode Array  For ESD and Latch-Up Protection"
U12 U13: library part D-261-0000, "MT48LC16M16A2TG, 256 Mbit High-Speed CMOS SDRAM, 16Mb x 16Bit x 4 Banks, TSOP54"
U14 U15 U16 U17 U47: library part D-260-0000, "K6R4016V1D-TC10T, 256K x 16-Bit SRAM, TSOP44"
U18 U55 U62 U63 U64: library part D-204-0001, "NUP2201MR6, Low Capacitance Diode Array, USB Protection"
U19 U56: library part D-221-0004, "CY7C68001-56LFC, EZ-USB SX2 High-Speed USB Interface"
U21: library part D-222-0000, "THS8134BCPHP, Triple 8-Bit, 80 MSPS Video DAC with Tri-Level Sync Generation"
U23: library part D-263-0008, "EEPROM, 1-wire, 1024-bit, Surface Mount"
U24: library part D-220-0004, "ADC084S021, 8-bit ADC, 4 Channel, 50 ksps to 200ksps, SPI"
U26: library part D-201-0007, "PT2300, 2W x 2 Class AB Audio Power Amplifier"
U27: library part D-206-0006, "PCF2123TS, SPI Real time clock/calendar, TSSOP14"
U28: library part D-222-0004, "DAC084S085CIMM, Quad 8-bit, Single 2.7V to 5.5V rail-to-rail output"
U30: library part D-241-0024, "FPGA, Xilinx Spartan3-400 Standard Speed, BGA 1.0mm pitch, 400 balls, 0 to 85 degC"
U31 U32 U33 U34 U35: library part D-205-0004, "HEX Inverter"
U36: library part D-152-0003, "OPTOISOLATOR; SMD; Transistor output"
U39 U40 U41: library part D-204-0033, "AP1084KL, 5A Low Dropout Positive Adjustable Regulator"
U42: library part D-204-0034, "NCP630A, 3.0A Fast Linear Voltage Regulator, D2PAK"
U43 U44 U58: library part D-204-0035, "TC1017R-3.3VLTTR, 3.3V Micropower Low Dropout Regulator, 5-Pin SC70-5"
U45 U49 U60: library part D-243-0000, "MAX6315, Open-Drain Output SOT Reset IC, Customized Reset Thresholds, Timeout Delays"
U46: library part D-221-0016, "ISL8491IB, RS-485/RS-422 Transceivers"
U48: library part D-202-0006, "XPT2046, Touch Screen Controller"
U50 U51 U52 U53: library part D-262-0006
U59: library part D-221-0017, "HIN232ACBNZ-T 5V,  True RS-232 Transceivers"
U61: library part D-221-0018, "Hi-Speed Universal Serial Bus host controller"
UH1 UH2: library part D-300-0021, "Header IDC, 2 x 10 Pin Vertical 2.54mm Pitch (Non-Boxed, Male)"
VR1: library part D-105-0001, "Potentiometer, 2 x 5K Linear 9mm PCB Mount Fluted Shaft"
Y1: library part D-103-0012, "Crystal, SMD, 20.000000MHz Stab=30ppm 20.0pF"
Y2: library part D-103-0030, "Crystal, SMD, 25.000000MHz Stab=50ppm 18.0pF"
Y3: library part D-103-0031, "Crystal, 32.768 KHz Surface Mount"
Y4: library part D-103-0013, "Crystal, SMD, 24.000000MHz Stab=30ppm 20.0pF"
Y5: library part D-103-0000, "Crystal, SMD, 12.000000MHz Stab=30ppm 20.0pF"

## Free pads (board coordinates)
  rect 236.22x236.22 hole 161.42: 0(-733.79,1574.73) 0(-733.79,6052.56) 0(8413.75,6052.57) 0(8413.75,1574.73)
  round 122.05 hole 122.05 unplated: 1(-726.95,4502.25) 1(8406.91,4502.25)

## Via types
v1: diameter 23, hole 11.81, Top Layer to Bottom Layer, 3672 vias
v2: diameter 26, hole 11.81, Top Layer to Bottom Layer, 461 vias
v3: diameter 19, hole 11.81, Top Layer to Bottom Layer, tented both sides, 396 vias
v4: diameter 23.62, hole 11.81, Top Layer to Bottom Layer, 288 vias
v5: diameter 20, hole 11.81, Top Layer to Bottom Layer, 91 vias
v6: diameter 23, hole 11.81, Top Layer to Bottom Layer, tented both sides, 50 vias
v7: diameter 31, hole 11.81, Top Layer to Bottom Layer, 15 vias
v8: diameter 27.56, hole 11.81, Top Layer to Bottom Layer, tented both sides, 4 vias
v9: diameter 29, hole 11.81, Top Layer to Bottom Layer, 3 vias
v10: diameter 21, hole 11.81, Top Layer to Bottom Layer, 1 vias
